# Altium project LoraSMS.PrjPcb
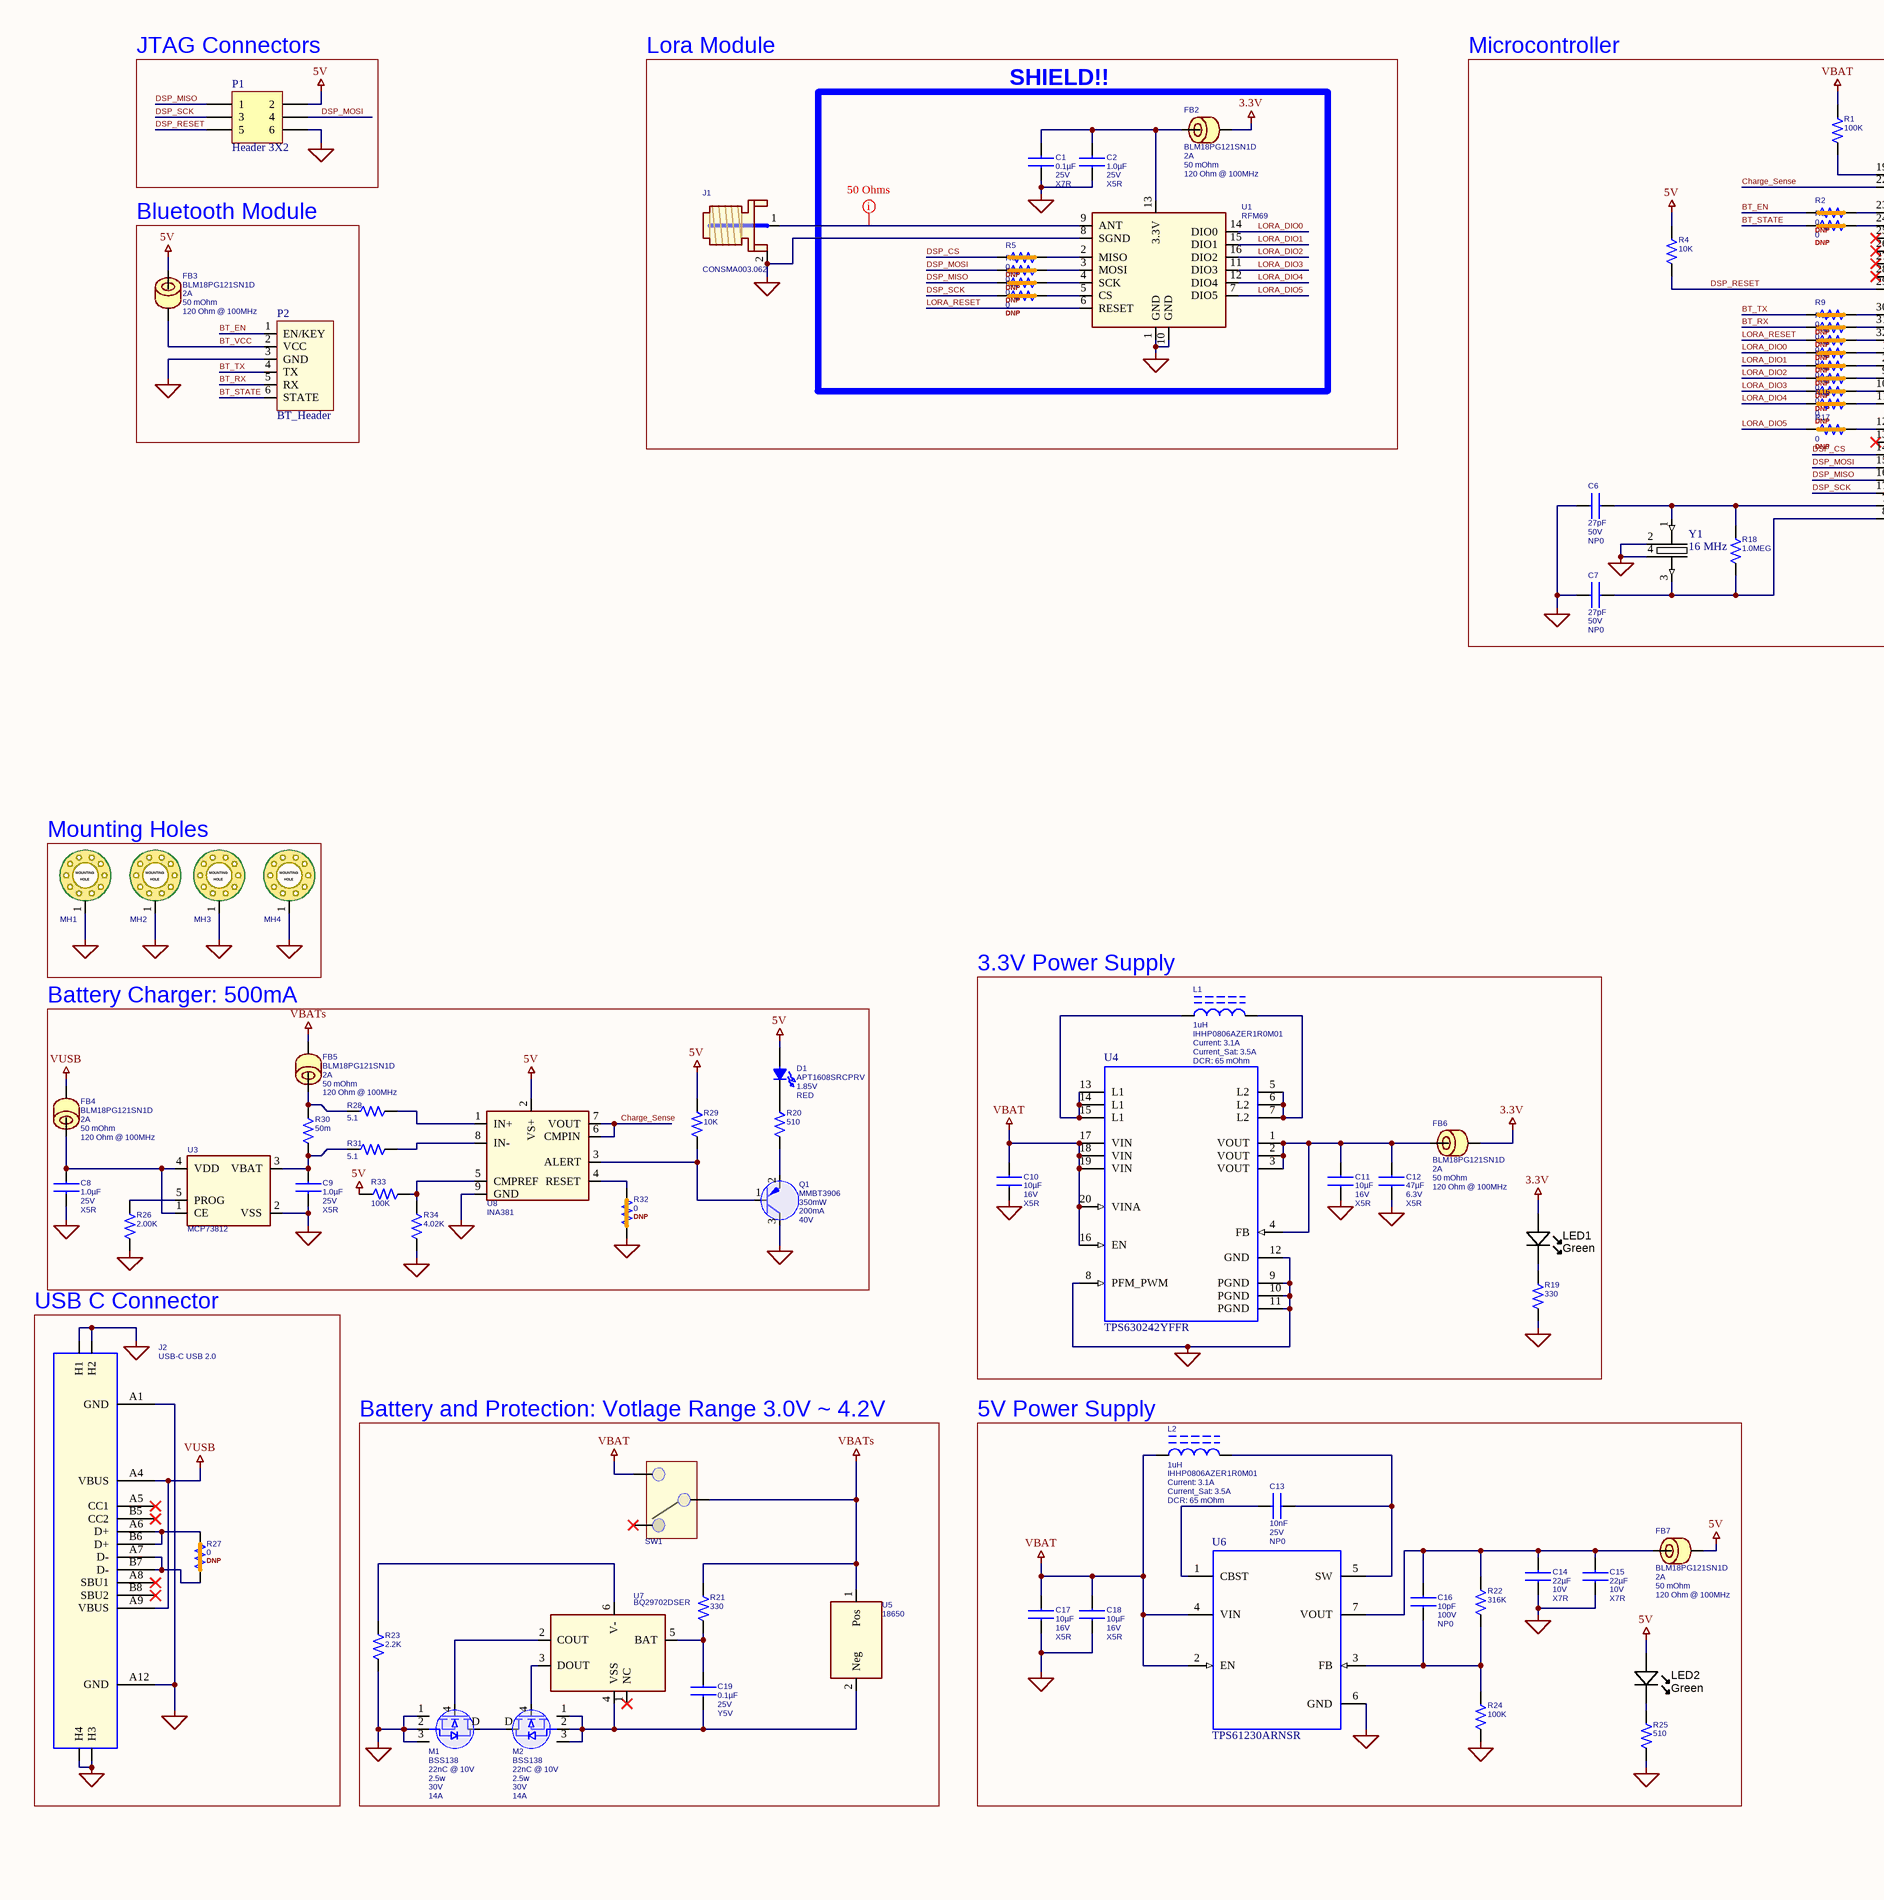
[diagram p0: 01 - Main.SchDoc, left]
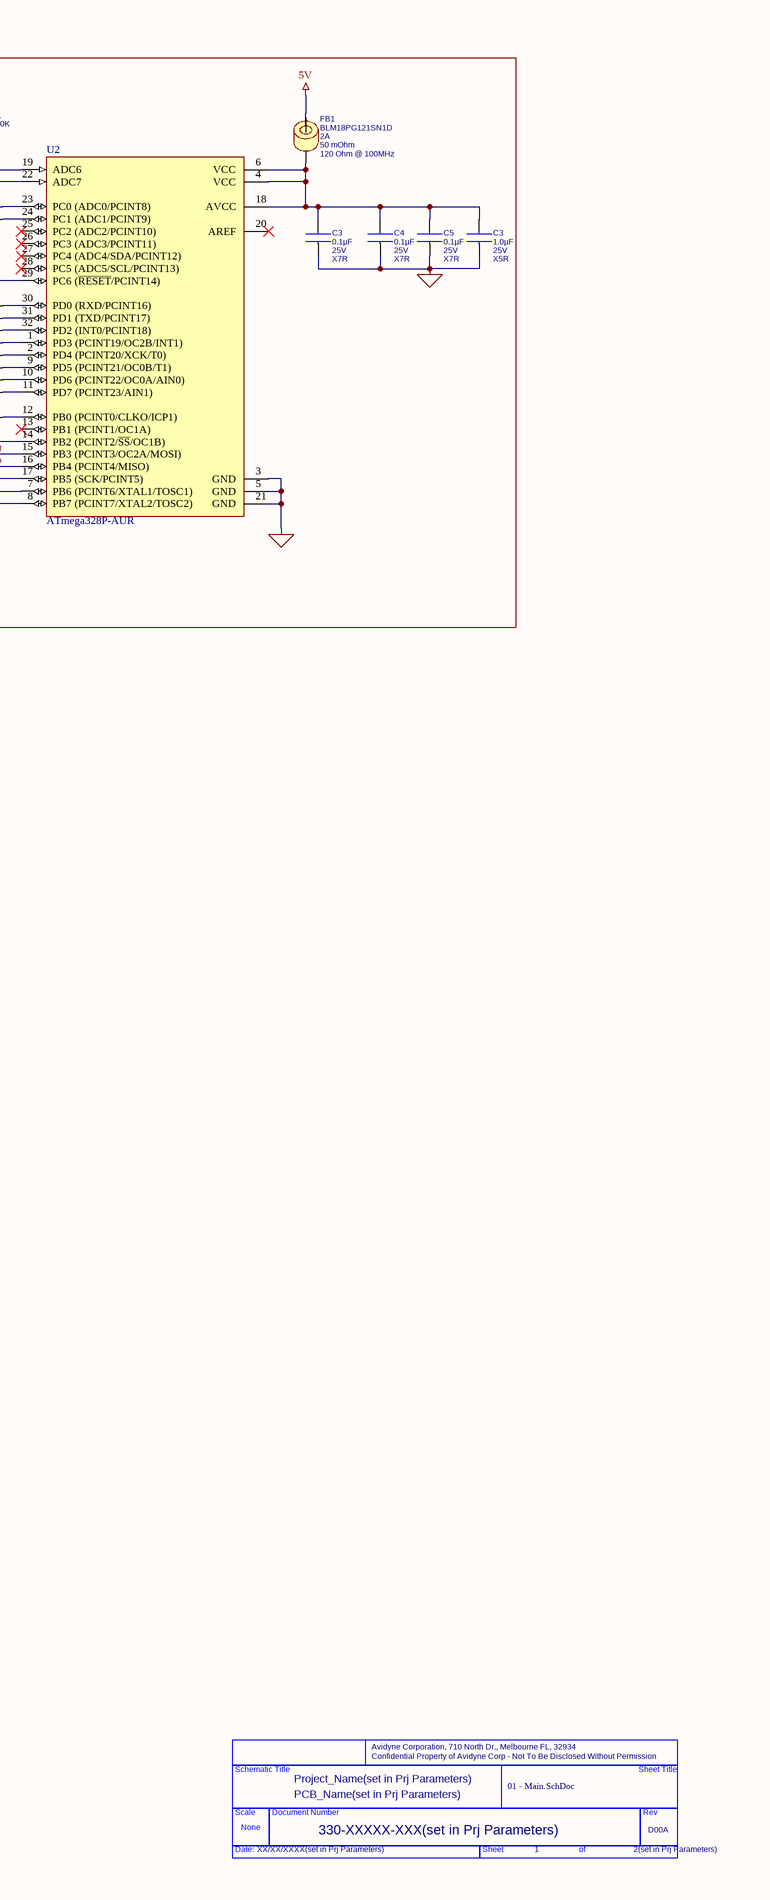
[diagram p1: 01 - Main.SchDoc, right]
prj_par_310_AviPrtNum: 310-XXXXX-XXX(set in Prj Parameters); prj_par_310_ReleaseDate: XX/XX/XXXX(set in Prj Parameters); prj_par_310_REV: D00A; prj_par_330_AviPrtNum: 330-XXXXX-XXX(set in Prj Parameters); prj_par_330_ReleaseDate: XX/XX/XXXX(set in Prj Parameters); prj_par_330_REV: D00A; prj_par_330_Sheet_Total: 2(set in Prj Parameters); prj_par_340_AviPrtNum: 340-XXXXX-XXX(set in Prj Parameters); prj_par_340_ReleaseDate: XX/XX/XXXX(set in Prj Parameters); prj_par_340_REV: D00A; prj_par_350_AviPrtNum: 350-XXXXX-XXX(set in Prj Parameters); prj_par_350_ReleaseDate: XX/XX/XXXX(set in Prj Parameters); prj_par_350_REV: D00A; prj_par_360_AviPrtNum: 360-XXXXX-XXX(set in Prj Parameters); prj_par_360_ReleaseDate: XX/XX/XXXX(set in Prj Parameters); prj_par_360_REV: D00A; prj_par_Address_AvidyneCorp: Avidyne Corporation, 710 North Dr., Melbourne FL, 32934; prj_par_ConfProp_AvidyneCorp: Confidential Property of Avidyne Corp - Not To Be Disclosed Without Permission; prj_par_PCB_Name: PCB_Name(set in Prj Parameters); prj_par_Project_Name: Project_Name(set in Prj Parameters)
1 sheet, 88 parts. Net scope: flat (ports and power ports of the same name join across sheets).
Board file: 340-XXXXX-XXX.PcbDoc

## Sheet 01 - Main.SchDoc: SetInProjOptions
size 513 x 386 mm; Date: SetInProjOptions; DocumentNumber: SetInProjOptions; Revision: SetInProjOptions; SheetNumber: 1; SheetTotal: SetInProjOptions

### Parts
(Parts that share a designator on the sheet are numbered #1, #2 ... from top to bottom, then left to right.)
*?  R_E_V: D00A  P_C_B_Name: PCB_Name(set in Prj Parameters)  Proj_Name: Project_Name(set in Prj Parameters)  SheetTitle: 01 - Main.SchDoc  Page Count: 2(set in Prj Parameters)  Page Number: 1  Doc: 330-XXXXX-XXX(set in Prj Parameters)  (graphical)
C1  0.1µF  VOLTAGE: 25V  DIELECTRIC: X7R  [CAPC1608X95N]
C2  1.0µF  VOLTAGE: 25V  DIELECTRIC: X5R  [CAPC1608X95N]
C3#1  0.1µF  VOLTAGE: 25V  DIELECTRIC: X7R  [CAPC1608X95N]
C3#2  1.0µF  VOLTAGE: 25V  DIELECTRIC: X5R  [CAPC1608X95N]
C4  0.1µF  VOLTAGE: 25V  DIELECTRIC: X7R  [CAPC1608X95N]
C5  0.1µF  VOLTAGE: 25V  DIELECTRIC: X7R  [CAPC1608X95N]
C6  27pF  VOLTAGE: 50V  DIELECTRIC: NP0  [CAPC1608X95N]
C7  27pF  VOLTAGE: 50V  DIELECTRIC: NP0  [CAPC1608X95N]
C8  1.0µF  VOLTAGE: 25V  DIELECTRIC: X5R  [CAPC1608X95N]
C9  1.0µF  VOLTAGE: 25V  DIELECTRIC: X5R  [CAPC1608X95N]
C10  10µF  VOLTAGE: 16V  DIELECTRIC: X5R  [CAPC2013X140N]
C11  10µF  VOLTAGE: 16V  DIELECTRIC: X5R  [CAPC2013X140N]
C12  47µF  VOLTAGE: 6.3V  DIELECTRIC: X5R  [CAPC2013X140N]
C13  10nF  VOLTAGE: 25V  DIELECTRIC: NP0  [CAPC1608X95N]
C14  22µF  VOLTAGE: 10V  DIELECTRIC: X7R  [CAPC2013X140N]
C15  22µF  VOLTAGE: 10V  DIELECTRIC: X7R  [CAPC2013X140N]
C16  10pF  VOLTAGE: 100V  DIELECTRIC: NP0  [CAPC1608X95N]
C17  10µF  VOLTAGE: 16V  DIELECTRIC: X5R  [CAPC2013X140N]
C18  10µF  VOLTAGE: 16V  DIELECTRIC: X5R  [CAPC2013X140N]
C19  0.1µF  VOLTAGE: 25V  DIELECTRIC: Y5V  [CAPC1608X95N]
D1  APT1608SRCPRV  Vf: 1.85V  LED_COLOR: RED  [LEDM1608X90N]
FB1  BLM18PG121SN1D  Current: 2A  DCR: 50 mOhm  Impedance: 120 Ohm @ 100MHz  [INDC1608X95N]
FB2  BLM18PG121SN1D  Current: 2A  DCR: 50 mOhm  Impedance: 120 Ohm @ 100MHz  [INDC1608X95N]
FB3  BLM18PG121SN1D  Current: 2A  DCR: 50 mOhm  Impedance: 120 Ohm @ 100MHz  [INDC1608X95N]
FB4  BLM18PG121SN1D  Current: 2A  DCR: 50 mOhm  Impedance: 120 Ohm @ 100MHz  [INDC1608X95N]
FB5  BLM18PG121SN1D  Current: 2A  DCR: 50 mOhm  Impedance: 120 Ohm @ 100MHz  [INDC1608X95N]
FB6  BLM18PG121SN1D  Current: 2A  DCR: 50 mOhm  Impedance: 120 Ohm @ 100MHz  [INDC1608X95N]
FB7  BLM18PG121SN1D  Current: 2A  DCR: 50 mOhm  Impedance: 120 Ohm @ 100MHz  [INDC1608X95N]
J1  CONSMA003.062  [LINX_CONSMA003.062]
J2  USB-C USB 2.0  [GCT_USB4110-GF-A]
L1  1uH  Manufacturer P/N: IHHP0806AZER1R0M01  Current: 3.1A  Current_Sat: 3.5A  DCR: 65 mOhm  [INDC2016X10N]
L2  1uH  Manufacturer P/N: IHHP0806AZER1R0M01  Current: 3.1A  Current_Sat: 3.5A  DCR: 65 mOhm  [INDC2016X10N]
LED1  Green  [LED-0603-GREEN]
LED2  Green  [LED-0603-GREEN]
M1  BSS138  Qg: 22nC @ 10V  Wattage: 2.5w  Vdss: 30V  Id: 14A  [VISHAY_POWERPAK-SO-8-SINGLE]
M2  BSS138  Qg: 22nC @ 10V  Wattage: 2.5w  Vdss: 30V  Id: 14A  [VISHAY_POWERPAK-SO-8-SINGLE]
MH1  MOUNTING HOLE  [MHOLE-120-280]  (value not drawn)
MH2  MOUNTING HOLE  [MHOLE-120-280]  (value not drawn)
MH3  MOUNTING HOLE  [MHOLE-120-280]  (value not drawn)
MH4  MOUNTING HOLE  [MHOLE-120-280]  (value not drawn)
P1  Header 3X2  [HDR2X3]
P2  BT_Header  [BT_MODULE]
Q1  MMBT3906  Wattage: 350mW  Current: 200mA  Voltage: 40V  [SOT95P240X115-3N]
R1  100K  [RESC1608X84N]
R2  0  Do Not Populate: DNP  [RESC1005X40N_SHORT]  (net tie)
R3  0  Do Not Populate: DNP  [RESC1005X40N_SHORT]  (net tie)
R4  10K  [RESC1608X84N]
R5  0  Do Not Populate: DNP  [RESC1005X40N_SHORT]  (net tie)
R6  0  Do Not Populate: DNP  [RESC1005X40N_SHORT]  (net tie)
R7  0  Do Not Populate: DNP  [RESC1005X40N_SHORT]  (net tie)
R8  0  Do Not Populate: DNP  [RESC1005X40N_SHORT]  (net tie)
R9  0  Do Not Populate: DNP  [RESC1005X40N_SHORT]  (net tie)
R10  0  Do Not Populate: DNP  [RESC1005X40N_SHORT]  (net tie)
R11  0  Do Not Populate: DNP  [RESC1005X40N_SHORT]  (net tie)
R12  0  Do Not Populate: DNP  [RESC1005X40N_SHORT]  (net tie)
R13  0  Do Not Populate: DNP  [RESC1005X40N_SHORT]  (net tie)
R14  0  Do Not Populate: DNP  [RESC1005X40N_SHORT]  (net tie)
R15  0  Do Not Populate: DNP  [RESC1005X40N_SHORT]  (net tie)
R16  0  Do Not Populate: DNP  [RESC1005X40N_SHORT]  (net tie)
R17  0  Do Not Populate: DNP  [RESC1005X40N_SHORT]  (net tie)
R18  1.0MEG  [RESC1608X84N]
R19  330  [RESC2013X84N]
R20  510  [RESC1608X84N]
R21  330  [RESC1608X84N]
R22  316K  [RESC1608X84N]
R23  2.2K  [RESC1608X84N]
R24  100K  [RESC1608X84N]
R25  510  [RESC1608X84N]
R26  2.00K  [RESC1608X84N]
R27  0  Do Not Populate: DNP  [RESC1005X40N_SHORT]  (net tie)
R28  5.1  [RESC1608X84N]
R29  10K  [RESC1608X84N]
R30  50m  [RESC3216X84N]
R31  5.1  [RESC1608X84N]
R32  0  Do Not Populate: DNP  [RESC1005X40N_SHORT]  (net tie)
R33  100K  [RESC1608X84N]
R34  4.02K  [RESC1608X84N]
SW1  SWITCH  [JS202011JAQN]  (value not drawn)
U1  RFM69  [RFM69HCW]
U2  ATmega328P-AUR  [32A_N]
U3  MCP73812  [SOT95P280X145-5N]
U4  TPS630242YFFR  [YFF0020AEBA]
U5  18650  [18650]
U6  N/A  [RNS0007A]  (value not drawn)
U7  BQ29702DSER  [SOTFL50P162X60-6N]
U8  INA381  [SON45P200X200X80-9N]
Y1  16 MHz  [Crystal_2.5x2.0]

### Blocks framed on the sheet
JTAG Connectors: P1
Lora Module: J1
Microcontroller: C3#1 C3#2 C4-C7 FB1 R1-R4 R9-R18 U2 Y1
SHIELD!!: C1 C2 FB2 R5-R8 U1
Bluetooth Module: FB3 P2
Mounting Holes: MH1-MH4
3.3V Power Supply: C10-C12 FB6 L1 LED1 R19 U4
Battery Charger: 500mA: C8 C9 D1 FB4 FB5 Q1 R20 R26 R28-R34 U3 U8
USB C Connector: J2 R27
Battery and Protection: Votlage Range 3.0V ~ 4.2V: C19 M1 M2 R21 R23 SW1 U5 U7
5V Power Supply: C13-C18 FB7 L2 LED2 R22 R24 R25 U6

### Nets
3.3V: FB2.2 FB6.2 LED1.A
5V: D1.A(ANODE) FB1.1 FB3.1 FB7.2 LED2.A P1.2 R4.1 R29.1 R33.1 U8.2(VS+)
GND: C1.2 C2.2 C3#1.2 C3#2.2 C4.2 C5.2 C6.1 C7.1 C8.2 C9.2 C10.2 C11.2 C12.2 C14.2 C15.2 C17.2 C18.2 J1.2(SHIELD) J2.A1(GND) J2.A12(GND) J2.H1 J2.H2 J2.H3 J2.H4 M1.1(SOURCE) M1.2(SOURCE) M1.3(SOURCE) MH1.1 MH2.1 MH3.1 MH4.1 P1.6 P2.3(GND) Q1.3(C) R19.2 R23.2 R24.2 R25.2 R26.2 R32.1 R34.2 U1.1(GND) U1.8(SGND) U1.10(GND) U2.3(GND) U2.5(GND) U2.21(GND) U3.2(VSS) U4.8(PFM_PWM) U4.9(PGND) U4.10(PGND) U4.11(PGND) U4.12(GND) U6.6(GND) U8.9(GND) Y1.2(GND) Y1.4(GND)
VBAT: C10.1 C17.1 C18.1 L2.1 R1.1 SW1.1 U4.16(EN) U4.17(VIN) U4.18(VIN) U4.19(VIN) U4.20(VINA) U6.2(EN) U6.4(VIN)
VBATs: FB5.2 R21.1 SW1.2 U5.1(Pos)
VUSB: FB4.2 J2.A4(VBUS) J2.A9(VBUS)
BT_EN: P2.1(EN/KEY) R2.1
BT_RX: P2.5(RX) R10.1
BT_STATE: P2.6(STATE) R3.1
BT_TX: P2.4(TX) R9.1
BT_VCC: FB3.2 P2.2(VCC)
Charge_Sense: U2.22(ADC7) U8.6(CMPIN) U8.7(VOUT)
DSP_CS: R5.1 U2.14(PB2_(PCINT2/~{SS}/OC1B))
DSP_MISO: P1.1 R7.1 U2.16(PB4_(PCINT4/MISO))
DSP_MOSI: P1.4 R6.1 U2.15(PB3_(PCINT3/OC2A/MOSI))
DSP_RESET: P1.5 R4.2 U2.29(PC6_(~{RESET}/PCINT14))
DSP_SCK: P1.3 R8.1 U2.17(PB5_(SCK/PCINT5))
LORA_DIO0: R12.1 U1.14(DIO0)
LORA_DIO1: R13.1 U1.15(DIO1)
LORA_DIO2: R14.1 U1.16(DIO2)
LORA_DIO3: R15.1 U1.11(DIO3)
LORA_DIO4: R16.1 U1.12(DIO4)
LORA_DIO5: R17.1 U1.7(DIO5)
LORA_RESET: R11.1 U1.6(RESET)
NetC1_1: C1.1 C2.1 FB2.1 U1.13(3.3V)
NetC3#1_1: C3#1.1 C3#2.1 C4.1 C5.1 FB1.2 U2.4(VCC) U2.6(VCC) U2.18(AVCC)
NetC6_2: C6.2 R18.1 U2.7(PB6_(PCINT6/XTAL1/TOSC1)) Y1.1
NetC7_2: C7.2 R18.2 U2.8(PB7_(PCINT7/XTAL2/TOSC2)) Y1.3
NetC8_1: C8.1 FB4.1 U3.1(CE) U3.4(VDD)
NetC9_1: C9.1 R30.2 R31.1 U3.3(VBAT)
NetC11_1: C11.1 C12.1 FB6.1 U4.1(VOUT) U4.2(VOUT) U4.3(VOUT) U4.4(FB)
NetC13_1: C13.1 U6.1(CBST)
NetC13_2: C13.2 L2.2 U6.5(SW)
NetC14_1: C14.1 C15.1 C16.1 FB7.1 R22.1 U6.7(VOUT)
NetC16_2: C16.2 R22.2 R24.1 U6.3(FB)
NetC19_1: C19.1 R21.2 U7.5(BAT)
NetC19_2: C19.2 M2.1(SOURCE) M2.2(SOURCE) M2.3(SOURCE) U5.2(Neg) U7.4(VSS)
NetD1_C: D1.C(CATHODE) R20.1
NetFB5_1: FB5.1 R28.1 R30.1
NetJ1_1: J1.1(CENTER) U1.9(ANT)
NetJ2_A6: J2.A6(D+) J2.B6(D+) R27.2
NetJ2_A7: J2.A7(D-) J2.B7(D-) R27.1
NetL1_1: L1.1 U4.13(L1) U4.14(L1) U4.15(L1)
NetL1_2: L1.2 U4.5(L2) U4.6(L2) U4.7(L2)
NetLED1_K: LED1.K R19.1
NetLED2_K: LED2.K R25.1
NetM1_4: M1.4(GATE) U7.2(COUT)
NetM1_D: M1.D(DRAIN) M2.D(DRAIN)
NetM2_4: M2.4(GATE) U7.3(DOUT)
NetQ1_1: Q1.1(B) R29.2 U8.3(ALERT)
NetQ1_2: Q1.2(E) R20.2
NetR1_2: R1.2 U2.19(ADC6)
NetR2_2: R2.2 U2.23(PC0_(ADC0/PCINT8))
NetR3_2: R3.2 U2.24(PC1_(ADC1/PCINT9))
NetR5_2: R5.2 U1.2(MISO)
NetR6_2: R6.2 U1.3(MOSI)
NetR7_2: R7.2 U1.4(SCK)
NetR8_2: R8.2 U1.5(CS)
NetR9_2: R9.2 U2.30(PD0_(RXD/PCINT16))
NetR10_2: R10.2 U2.31(PD1_(TXD/PCINT17))
NetR11_2: R11.2 U2.32(PD2_(INT0/PCINT18))
NetR12_2: R12.2 U2.1(PD3_(PCINT19/OC2B/INT1))
NetR13_2: R13.2 U2.2(PD4_(PCINT20/XCK/T0))
NetR14_2: R14.2 U2.9(PD5_(PCINT21/OC0B/T1))
NetR15_2: R15.2 U2.10(PD6_(PCINT22/OC0A/AIN0))
NetR16_2: R16.2 U2.11(PD7_(PCINT23/AIN1))
NetR17_2: R17.2 U2.12(PB0_(PCINT0/CLKO/ICP1))
NetR23_1: R23.1 U7.6(V-)
NetR26_1: R26.1 U3.5(PROG)
NetR28_2: R28.2 U8.1(IN+)
NetR31_2: R31.2 U8.8(IN-)
NetR32_2: R32.2 U8.4(RESET)
NetR33_2: R33.2 R34.1 U8.5(CMPREF)

Not connected (* = marked no-connect by the designer): J2 A5(CC1)* A8(SBU1)* B5(CC2)* B8(SBU2)*; SW1 3*; U2 13(PB1_(PCINT1/OC1A))* 20(AREF)* 25(PC2_(ADC2/PCINT10))* 26(PC3_(ADC3/PCINT11))* 27(PC4_(ADC4/SDA/PCINT12))* 28(PC5_(ADC5/SCL/PCINT13))*; U7 1(NC)*

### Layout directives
net class 50 Ohms: NetJ1_1

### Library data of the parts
*? = Fox_PrjLvl_TitleBlock
C1 C3#1 C4 C5 = 060-00124-000: CAP, CER, SMT, 25V, +/- 10%, X7R, 0603; Manufacturer: Kemet Corporation; Manufacturer P/N: C0603C104K3RAC; Value (nF): 100; Value (pF): 100000; Value (µF): 0.1
C2 C3#2 C8 C9 = 060-00192-001: CAP, CER, SMT, 1.0UF, 25V, 10%, X5R, 0603; Manufacturer: Kemet Corporation; Manufacturer P/N: C0603C105K3PAC; Value (nF): 1000; Value (pF): 1000000; Value (µF): 1
C6 C7 = 060-00139-005: CAP, CER, 10%, 50V, 27PF, CAP0603; Manufacturer: Kemet Corporation; Manufacturer P/N: C0603C270K5GAC; Value (nF): 0.027; Value (pF): 27; Value (µF): 0.000027
C10 C11 C17 C18 = 060-00196-000: CAP, CER, 10UF, 16V, X5R, 0805; Manufacturer: Murata Manufacturing Co., Ltd.; Manufacturer P/N: GRM21BR61C106KE15L; TOLERANCE: 10%; Value (nF): 10000; Value (pF): 10000000; Value (µF): 10
C12 = 060-00269-000: CAP, CER, 0805, 20%, 6.3V, X5R, 47UF; Manufacturer: Kemet Corporation; Manufacturer P/N: C0805C476M9PACTU; Value (nF): 47000; Value (pF): 47000000; Value (µF): 47
C13 = 060-00243-000: CAP, CER, 5%, 25V, C0G, 0603, 10,000PF; Manufacturer: TDK Corporation; Manufacturer P/N: C1608C0G1E103JT; Value (nF): 10; Value (pF): 10000; Value (µF): 0.01
C14 C15 = 060-00268-000: CAP, CER, 0805, 20%, 10V, X7R, 22UF; Manufacturer: Taiyo Yuden USA, Inc.; Manufacturer P/N: LMK212BJ226MG-T; Value (nF): 22000; Value (pF): 22000000; Value (µF): 22
C16 = 064-00028-016: CAP RF, HIQ, NPO, +/-1%, 10GHZ, 200, 100V, 0603, 10PF, ROHS; Manufacturer: Vishay; Manufacturer P/N: VJ0603D100FXBA; TOLERANCE: 1%; Value (nF): 0.01; Value (pF): 10; Value (µF): 0.00001
C19 = 060-00041-000: CAP, CER, SMT, 25V, +80/-20%,Y5V,0603,.1uf; Manufacturer: Kemet Corporation; Manufacturer P/N: C0603C104M3VAC; TOLERANCE: 20%; Value (nF): 100; Value (pF): 100000; Value (µF): 0.1
D1 = 023-00316-000: DIODE, LED, RED, SMT, 2.5V, 0603; Manufacturer: Kingbright; Candela: 100mcd; Wattage: 75mW; Wavelength: 640nm; Current: 20mA
FB1-FB7 = 082-00014-004: FERRITE,100MHZ,0603,25%,120OHM ROHS; Manufacturer: Murata
J1 = 030-00761-000: CONN, SMA JACK, FEMALE, EDGE; Manufacturer: LINX
J2 = USB4110-GF-A: CONN USB 2.0 TYPE-C R/A SMT; Manufacturer: GCT; Avidyne P/N: 030-00779-000; Contacts: 24
L1 L2 = 080-00223-000: INDUCTOR POWER 1UH 1.5A SMD; Manufacturer: Vishay Dale; TOLERANCE: 20%
LED1 LED2 = LED_SMD_Green_0603_570nm: LED 0603 SMD Green 570nm 50mcd 20mA; Manufacturer 1: Kingbright Company LLC; Manufacturer Part Number 1: APT1608CGCK; Material: AlGaInP; Ratings: 20mcd min; 50 mcd typ; 570 nm; Voltage - Forward (Vf) Typ: 2.1V; Viewing Angle: 120°; Lens Style/Size: Rectangle with Flat Top, 1.1mm x 0.8mm; Voltage - Forward (Vf) @ 10mA: 2.0V; SCDType: source; Wavelength - Peak: 574nm; Lens Type: Clear
M1 M2 = FDMS7692: MOSFET N-CH 30V 14A POWER56; Manufacturer: ON Semiconductor; Rds(on): 7.5 Ohm; Vgs(th): 3V @ 250UA
MH1-MH4 = MHOLE-120-280
P1 = Header 3X2: Header, 3-Pin, Dual row
P2 = BT_Header: HC-05 BLUETOOTH MODULE
Q1 = 025-00001-000: TRANS,BJT,PNP,3906,SOT-23; Manufacturer: Fairchild Semiconductor; Gain: 100 @ 10mA
R1 R24 = 070-00486-037: RES, THICK FILM CHIP, SMT, 1/10W, 1%, 0603, 100K OHM; Manufacturer: Panasonic Electronic Devices, Corp.; Manufacturer P/N: ERJ3EKF1003V
R2 R3 R5-R17 R27 R32 = 070-00475-085_SHORT: RES, THICK FILM CHIP, 1/16W, 1%, RES0402, 0 OHM, ROHS, SHORT-IN-PAD!; Manufacturer: Vishay-Dale Intertechnology, Inc; Manufacturer P/N: CRCW04020000Z0ED
R4 R29 = 070-00470-014: RES, THICK FILM CHIP, SMT, 1/10W, 5%, 0603, 10K OHM; Manufacturer: Vishay-Dale Intertechnology, Inc; Manufacturer P/N: CRCW060310K0JNEA
R18 = 070-00305-000: RES, 1/10W, 5%, 0603, I MEG; Manufacturer: KOA-Speer Electronics, Inc.; Manufacturer P/N: RM73B1JT105J
R19 = 070-00072-000: RES, 1/8W, 5%, 0805, 330 OHM; Manufacturer: KOA-Speer Electronics, Inc.; Manufacturer P/N: RM73B2AT331J
R20 R25 = 070-00470-011: RES, THICK FILM CHIP, SMT, 1/10W, 5%, 0603, 510 OHM; Manufacturer: Panasonic Electronic Devices, Corp.; Manufacturer P/N: ERJ3GEYJ511V
R21 = 070-00442-000: RES, 1/16 W, 1%, 0603, 330 OHM; Manufacturer: Panasonic Electronic Devices, Corp.; Manufacturer P/N: ERJ-3ENF3300V; Wattage: 1/10W
R22 = 070-00486-071: RES, THICK FILM CHIP, SMT, 1/10W, 1%, 0603, 316K OHM; Manufacturer: Panasonic Electronic Devices, Corp.; Manufacturer P/N: ERJ3EKF3163V
R23 = 070-00208-000: RES, 1/10W, 5%, 0603, 2.2K OHM; Manufacturer: KOA-Speer Electronics, Inc.; Manufacturer P/N: RM73B1JT222J
R26 = 070-00415-000: RES, 1/16W, 1%, 0603, 2.00K OHM; Manufacturer: Panasonic Electronic Devices, Corp.; Manufacturer P/N: ERJ-3EKF2001V
R28 R31 = 070-00486-069: RES, THICK FILM CHIP, SMT, 1/10W, 1%, 0603, 5.1 OHM; Manufacturer: Panasonic Electronic Devices, Corp.; Manufacturer P/N: ERJ-3EKF5R1V
R30 = 070-00499-001: RES, THICK FILM, CURRENT SENSE, 1/2 W, 1%, RES1206, 0.05 OHMS; Manufacturer: TT Electronics, PLC; Manufacturer P/N: LRC-LR1206LF-01-R050-F; Wattage: 1/2W
R33 = 070-00113-000: RES,1/10W,1%,0603,100K OHM; Manufacturer: Panasonic Electronic Devices, Corp.; Manufacturer P/N: ERJ-3EKF1003V
R34 = 070-00597-000: RES, METAL FILM, 1/16W, .5%, 0603, SMD, 4.02K; Manufacturer: Susumu; Manufacturer P/N: RR0816P-4021-D-59H; TOLERANCE: 1%
SW1 = JS202011JAQN: SWITCH SLIDE DPDT 300MA 6V; Manufacturer P/N: C&K
U1 = LoRa Module: RFM69HCW WIRELESS TRANSCEIVER 91; Manufacturer P/N: COM-13909; Manufacturer: SparkFun; Avidyne P/N: 011-XXXXX-XXX; Current: 130mA; Voltage-Input: 1.8V ~ 3.6V
U2 = ATmega328P-AUR: 8-bit AVR Microcontroller, 32KB Flash, 1KB EEPROM, 2KB SRAM, 32-pin TQFP, Industrial Grade (-40°C to 85°C)
U3 = MCP73812: IC LI-ION/LI-POLY CTRLR SOT23-5; Manufacturer P/N: MCP73812T-420I/OT; Manufacturer: Microchip Technology; Avidyne P/N: 011-XXXXX-XXX; Current: 500mA; Voltage-Input: 3.75V ~ 6V
U4 = TPS630242YFFR: Manufacturer Name: Texas Instruments
U5 = 1042: HOLDER BATTERY 1CELL 18650 SMD; Manufacturer: Keystone Electronics
U6 = TPS61230ARNSR: Manufacturer Name: Texas Instruments
U7 = BQ29702DSER: IC LITHIUM BATT PROTECT 6-SON; Manufacturer: Texas instruments
U8 = INA381A3IDSGR: LOW COST CURRENT SENSOR WITH COM; Manufacturer: TI; Avidyne P/N: 011-XXXXX-XXX; Voltage-Input: 0V ~ 6V
Y1 = FA-20H: CRYSTAL 16.0000MHZ 8PF SMD; Manufacture PN: FA-20H 16.0000MF10Z-AJ0; Manufacture: EPSON; Voltage: 2.7V - 3.6V; Frequency Stability: 10 ppm

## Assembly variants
DoNotPopulate: all parts fitted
